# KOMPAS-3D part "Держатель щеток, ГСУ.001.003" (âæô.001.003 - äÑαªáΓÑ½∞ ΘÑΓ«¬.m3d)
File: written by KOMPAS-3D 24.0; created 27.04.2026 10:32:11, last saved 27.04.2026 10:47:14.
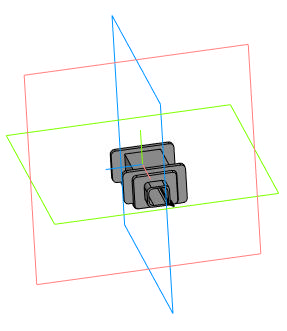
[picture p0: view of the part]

Document properties: Автор: User7; Полное имя файла: C:\Users\User7\Desktop\Двигатель мясорубки\ГСУ.001.003 - Держатель щеток.m3d

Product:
- Part/product: Держатель щеток  | designation ГСУ.001.003
    Масса: 0.006286

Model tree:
1. Эскиз:1
2. Элемент выдавливания:1
     Расстояние 1 = 1
3. Эскиз:2  (with: Грань.Элемент выдавливания:1, Ребро.Элемент выдавливания:1)
4. Элемент выдавливания:2
     Расстояние 1 = 11
5. Эскиз:3  (with: Грань.Элемент выдавливания:2, Ребро.Элемент выдавливания:1, Ребро.Элемент выдавливания:2)
6. Элемент выдавливания:3
     Расстояние 1 = 1
7. Эскиз:4  (with: Грань.Элемент выдавливания:3, Вершина.Элемент выдавливания:3)
8. Элемент выдавливания:4
9. Эскиз:5  (with: Грань.Элемент выдавливания:3, Вершина.Элемент выдавливания:4)
10. Скругление:1  (with: Ребро.Элемент выдавливания:4, Ребро.Элемент выдавливания:1)
     Радиус = 1
11. Скругление:2  (with: Ребро.Элемент выдавливания:3, Ребро.Элемент выдавливания:1)
     Радиус = 1
12. Элемент выдавливания:6
     Расстояние 1 = 0.5; Угол 1 = 25
13. Эскиз:6  (with: Грань.Элемент выдавливания:6, Ребро.Элемент выдавливания:6)
14. Элемент выдавливания:7  (with: Грань.Элемент выдавливания:1)
     Расстояние 1 = -17; Смещение 1 = 3.5
15. Скругление:3  (with: Ребро.Элемент выдавливания:7)
     Радиус = 1
16. Элемент выдавливания:8  (with: Грань.Элемент выдавливания:7)
     Расстояние 2 = 20
17. Эскиз:7  (with: Грань.Элемент выдавливания:8, Ребро.Элемент выдавливания:8)
18. Элемент выдавливания:9
     Расстояние 2 = 20

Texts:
  ГСУ.001.003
